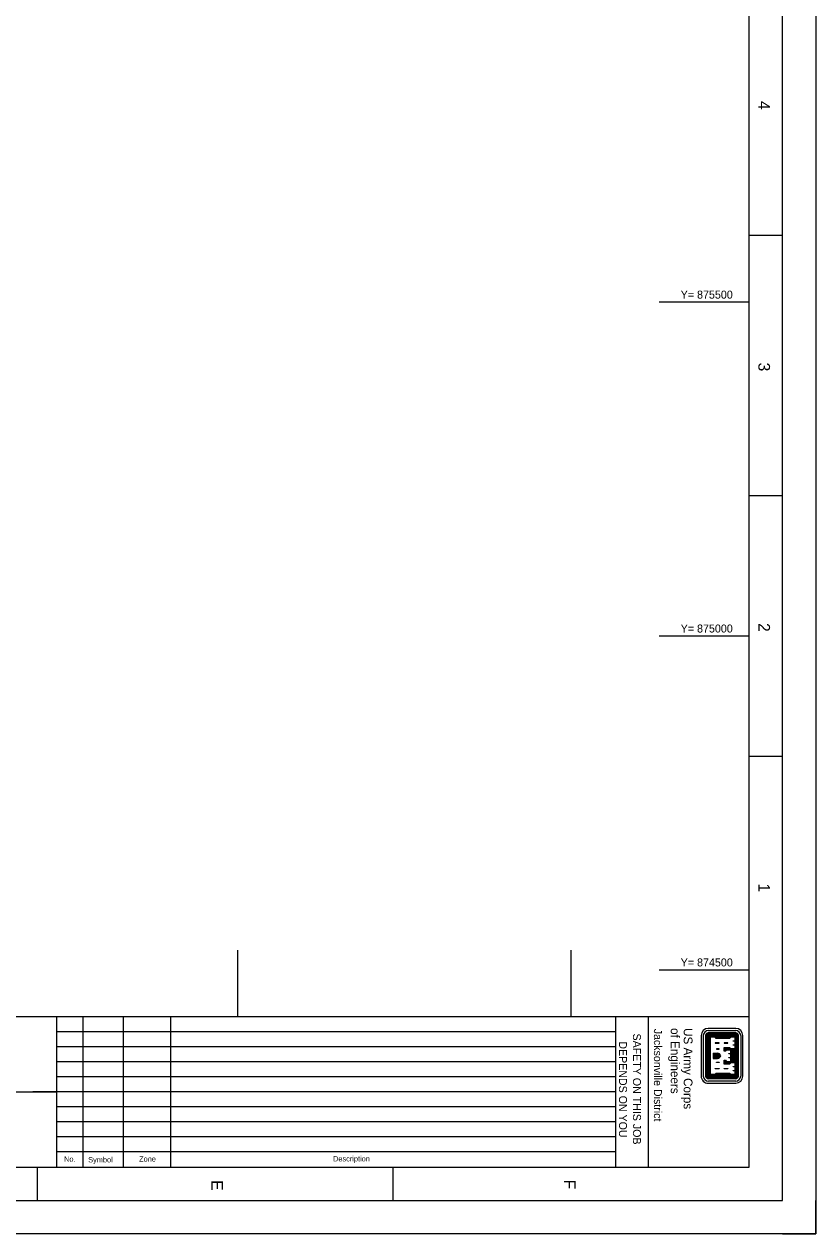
# Model space of a CAD drawing. Extents: x 573466 to 576866, y 874104 to 878505.
# Drawn here: x 575680 to 576866, y 874105 to 875916 of the extents above; entities that cross this region are included whole.
import ezdxf

# ---------------------------------------------------------------- set-up
doc = ezdxf.new("R2010")
doc.units = 0
for name, color, linetype in [('G-ANNO-NPLT', 7, 'Continuous'), ('G-ANNO-TEXT-LOGO', 7, 'Continuous'), ('G-ANNO-TEXT-TTLB', 7, 'Continuous'), ('G-ANNO-TTLB', 7, 'Continuous'), ('V-TOPO-COOR-STAT', 7, 'Continuous')]:
    doc.layers.add(name, color=color, linetype=linetype)

msp = doc.modelspace()

# ---------------------------------------------------------------- linework, layer by layer
at = {"layer": 'G-ANNO-NPLT'}
msp.add_lwpolyline([(576866.5, 878504.6), (576866.5, 874104.6), (573466.5, 874104.6), (573466.5, 878504.6)], close=True, dxfattribs=at)
msp.add_lwpolyline([(576816.5, 874104.6), (576866.5, 874104.6), (576866.5, 874154.6)], dxfattribs=at)
at = {"layer": 'G-ANNO-TEXT-LOGO'}
for p, q in [((576746.4, 874412.3), (576705.4, 874412.3)), ((576705.4, 874409.1), (576746.4, 874409.1)), ((576694.6, 874401.6), (576694.6, 874340.8)), ((576697.9, 874340.8), (576697.9, 874401.6)), ((576701.4, 874340.8), (576701.4, 874401.6)), ((576702.2, 874340.8), (576702.2, 874401.6)), ((576703.1, 874340.8), (576703.1, 874401.6)), ((576704, 874340.8), (576704, 874401.6)), ((576704.8, 874340.8), (576704.8, 874401.6)), ((576746.4, 874405.6), (576705.4, 874405.6)), ((576746.4, 874404.7), (576705.4, 874404.7)), ((576746.4, 874403.9), (576705.4, 874403.9)), ((576746.4, 874403), (576705.4, 874403)), ((576746.4, 874402.1), (576705.4, 874402.1)), ((576705.7, 874341.2), (576705.7, 874401.2)), ((576746.4, 874401.2), (576705.7, 874401.2)), ((576706.6, 874342), (576706.6, 874400.4)), ((576746.4, 874400.4), (576706.6, 874400.4)), ((576737.7, 874399.7), (576716.7, 874399.7)), ((576736.8, 874398.8), (576717.7, 874398.8)), ((576747, 874340.8), (576747, 874401.6)), ((576747.9, 874340.8), (576747.9, 874401.6)), ((576748.7, 874340.8), (576748.7, 874401.6)), ((576749.6, 874340.8), (576749.6, 874401.6)), ((576750.5, 874340.8), (576750.5, 874401.6)), ((576753.9, 874401.6), (576753.9, 874340.8)), ((576757.1, 874340.8), (576757.1, 874401.6)), ((576712.5, 874375.2), (576719.2, 874375.2)), ((576712.5, 874375.2), (576712.5, 874367.2)), ((576712.5, 874374.4), (576719.2, 874374.4)), ((576712.5, 874373.5), (576719.2, 874373.5)), ((576741, 874380.5), (576741, 874361.9)), ((576741.9, 874380.5), (576741.9, 874361.9)), ((576742.7, 874380.5), (576742.7, 874361.9)), ((576743.6, 874380.5), (576743.6, 874361.9)), ((576744.5, 874380.5), (576744.5, 874361.9)), ((576745.3, 874380.5), (576745.3, 874361.9)), ((576746.2, 874380.5), (576746.2, 874361.9)), ((576712.5, 874372.6), (576719.2, 874372.6)), ((576712.5, 874371.8), (576719.2, 874371.8)), ((576712.5, 874370.6), (576719.2, 874370.6)), ((576712.5, 874369.8), (576719.2, 874369.8)), ((576712.5, 874368.9), (576719.2, 874368.9)), ((576712.5, 874368), (576719.2, 874368)), ((576712.5, 874367.2), (576719.2, 874367.2)), ((576746.4, 874340.3), (576705.4, 874340.3)), ((576746.4, 874339.4), (576705.4, 874339.4)), ((576746.4, 874338.6), (576705.4, 874338.6)), ((576746.4, 874337.7), (576705.4, 874337.7)), ((576746.4, 874336.8), (576705.4, 874336.8)), ((576746.4, 874341.2), (576705.7, 874341.2)), ((576746.4, 874342), (576706.6, 874342)), ((576737.6, 874342.7), (576716.8, 874342.7)), ((576736.8, 874343.6), (576717.7, 874343.6)), ((576746.4, 874333.4), (576705.4, 874333.4)), ((576705.4, 874330.1), (576746.4, 874330.1))]:
    msp.add_line(p, q, dxfattribs=at)
for points in [[(576746.4, 874399.7), (576738.5, 874399.7), (576736.8, 874398), (576717.7, 874398), (576715.9, 874399.7), (576707.2, 874399.7), (576707.2, 874342.7), (576715.9, 874342.7), (576717.7, 874344.5), (576736.8, 874344.5), (576738.5, 874342.7), (576746.4, 874342.7), (576746.4, 874350.2), (576746.4, 874356), (576746.4, 874361.4), (576738.5, 874361.4), (576736.8, 874359.5), (576729.8, 874359.5), (576729.8, 874363.7), (576730.5, 874363.7), (576732.3, 874361.9), (576740.1, 874361.9), (576740.1, 874369.4), (576740.1, 874375.2), (576740.1, 874380.5), (576732.3, 874380.5), (576730.5, 874378.7), (576729.8, 874378.7), (576729.8, 874382.9), (576736.8, 874382.9), (576738.5, 874381.1), (576746.4, 874381.1), (576746.4, 874388.6), (576746.4, 874394.4), (576746.4, 874399.7)], [(576745.5, 874398.9), (576738.9, 874398.9), (576737.1, 874397.1), (576717.3, 874397.1), (576715.5, 874398.9), (576708.1, 874398.9), (576708.1, 874343.5), (576715.5, 874343.5), (576717.3, 874345.4), (576737.1, 874345.4), (576738.9, 874343.5), (576745.5, 874343.5), (576745.5, 874348.9), (576742.4, 874348.9), (576742.4, 874349.4), (576745.5, 874349.4), (576745.5, 874354.7), (576742.4, 874354.7), (576742.4, 874355.1), (576745.5, 874355.1), (576745.5, 874360.5), (576738.9, 874360.5), (576737.1, 874358.7), (576729, 874358.7), (576729, 874364.5), (576730.9, 874364.5), (576732.7, 874362.7), (576739.3, 874362.7), (576739.3, 874368.1), (576736.2, 874368.1), (576736.2, 874368.5), (576739.3, 874368.5), (576739.3, 874373.9), (576736.2, 874373.9), (576736.2, 874374.4), (576739.3, 874374.4), (576739.3, 874379.7), (576732.7, 874379.7), (576730.9, 874377.9), (576729, 874377.9), (576729, 874383.7), (576737.1, 874383.7), (576738.9, 874381.9), (576745.5, 874381.9), (576745.5, 874387.2), (576742.4, 874387.2), (576742.4, 874387.7), (576745.5, 874387.7), (576745.5, 874393.1), (576742.4, 874393.1), (576742.4, 874393.5), (576745.5, 874393.5), (576745.5, 874398.9)], [(576721.5, 874390.7), (576715.6, 874390.7), (576715.6, 874390.1), (576721.5, 874390.1), (576721.5, 874390.7)], [(576721.5, 874381.5), (576717.4, 874381.5), (576717.4, 874381), (576721.5, 874381), (576721.5, 874381.5)], [(576734.8, 874390.7), (576729, 874390.7), (576729, 874390.1), (576734.8, 874390.1), (576734.8, 874390.7)], [(576736.9, 874381.5), (576736.4, 874382), (576730.7, 874382), (576730.7, 874380.1), (576732, 874381.4), (576737, 874381.4)], [(576721.5, 874360.9), (576717.4, 874360.9), (576717.4, 874361.4), (576721.5, 874361.4), (576721.5, 874360.9)], [(576736.9, 874360.9), (576736.4, 874360.4), (576730.7, 874360.4), (576730.7, 874362.2), (576732, 874361), (576737, 874361)], [(576721.5, 874351.8), (576715.6, 874351.8), (576715.6, 874352.3), (576721.5, 874352.3), (576721.5, 874351.8)], [(576734.8, 874351.8), (576729, 874351.8), (576729, 874352.3), (576734.8, 874352.3), (576734.8, 874351.8)]]:
    msp.add_lwpolyline(points, dxfattribs=at)
for centre, major_axis, start_param, end_param in [((576705.3, 874401.5), (0, 10.7), 6.28317, 7.853966), ((576705.3, 874401.5), (0, 7.49), 6.28317, 7.853966), ((576746.4, 874401.5), (0, -10.7), 1.57078, 3.141576), ((576746.4, 874401.5), (0, -7.49), 1.57078, 3.141576), ((576705.3, 874401.5), (0, 4.02), 6.28317, 7.853966), ((576705.3, 874401.5), (0, 3.15), 6.28317, 7.853966), ((576705.3, 874401.5), (0, 2.28), 6.28317, 7.853966), ((576705.3, 874401.5), (0, 1.41), 6.28317, 7.853966), ((576705.3, 874401.5), (0, 0.546), 6.28317, 7.853966), ((576746.4, 874401.5), (0, -4.02), 1.57078, 3.141576), ((576746.4, 874401.5), (0, -3.15), 1.57078, 3.141576), ((576746.4, 874401.5), (0, -2.28), 1.57078, 3.141576), ((576746.4, 874401.5), (0, -1.41), 1.57078, 3.141576), ((576746.4, 874401.5), (0, -0.546), 1.57078, 3.141576), ((576718.7, 874369.7), (0, 3.82), 4.947465, 6.21436), ((576718.7, 874369.7), (0, 5.55), 4.985832, 6.214359), ((576718.7, 874369.7), (0, 4.69), 4.947465, 6.21436), ((576718.7, 874369.7), (0, 2.95), 4.947465, 6.21436), ((576718.7, 874372.7), (0, -2.08), 0.068794, 1.335689), ((576718.7, 874372.7), (0, -2.95), 0.068794, 1.335689), ((576718.7, 874369.7), (0, 2.08), 4.947465, 6.214359), ((576718.7, 874372.7), (0, -3.82), 0.068795, 1.335689), ((576718.7, 874372.7), (0, -4.69), 0.068795, 1.335689), ((576718.7, 874372.7), (0, -5.55), 0.068795, 1.29842), ((576705.3, 874340.8), (0, -10.7), 4.712373, 6.28317), ((576705.3, 874340.8), (0, 7.49), 1.570781, 3.141577), ((576705.3, 874340.8), (0, -4.02), 4.712373, 6.28317), ((576705.3, 874340.8), (0, -3.15), 4.712373, 6.28317), ((576705.3, 874340.8), (0, -2.28), 4.712373, 6.28317), ((576705.3, 874340.8), (0, -1.41), 4.712373, 6.28317), ((576705.3, 874340.8), (0, -0.546), 4.712373, 6.28317), ((576746.4, 874340.8), (0, -4.02), 6.283169, 7.853965), ((576746.4, 874340.8), (0, -3.15), 6.283169, 7.853965), ((576746.4, 874340.8), (0, -2.28), 6.283169, 7.853965), ((576746.4, 874340.8), (0, -1.41), 6.283169, 7.853965), ((576746.4, 874340.8), (0, -0.546), 6.283169, 7.853965), ((576746.4, 874340.8), (0, -10.7), 6.283169, 7.853965), ((576746.4, 874340.8), (0, -7.49), 6.28317, 7.853966)]:
    msp.add_ellipse(centre, major_axis=major_axis, ratio=0.99964, start_param=start_param, end_param=end_param, dxfattribs=at)
at = {"layer": 'G-ANNO-TTLB'}
for p, q in [((576816.5, 875599.6), (576766.5, 875599.6)), ((576816.5, 875209.6), (576766.5, 875209.6)), ((576816.5, 874819.6), (576766.5, 874819.6)), ((576766.5, 874429.6), (573566.5, 874429.6)), ((575728.2, 874429.6), (575728.2, 874204.6)), ((575768.1, 874429.6), (575768, 874204.6)), ((575828.1, 874429.6), (575828.1, 874204.6)), ((575899.2, 874429.6), (575899.2, 874204.6)), ((576566.1, 874430.2), (576566.1, 874205.2)), ((576615.2, 874429.6), (576615.2, 874204.6)), ((576566.1, 874407.3), (575728.2, 874407.3)), ((576566.1, 874384.8), (575728.2, 874384.8)), ((576566.1, 874362.3), (575728.2, 874362.3)), ((576566.1, 874339.8), (575728.2, 874339.8)), ((574868.6, 874317.8), (575728.2, 874317.1)), ((575728.2, 874317.1), (575692.8, 874317.1)), ((576566.1, 874317.3), (575728.2, 874317.3)), ((576566.1, 874294.8), (575728.2, 874294.8)), ((576566.1, 874272.3), (575728.2, 874272.3)), ((576566.1, 874249.8), (575728.2, 874249.8)), ((576566.1, 874227.3), (575728.2, 874227.3)), ((575699.7, 874154.6), (575699.7, 874204.6)), ((576233, 874154.6), (576233, 874204.6))]:
    msp.add_line(p, q, dxfattribs=at)
for points in [[(573516.5, 878454.6), (573516.5, 874154.6), (576816.5, 874154.6), (576816.5, 878454.6)], [(576766.5, 874204.6), (576766.5, 878329.6), (573566.5, 878329.6), (573566.5, 874204.6)]]:
    msp.add_lwpolyline(points, close=True, dxfattribs=at)
at = {"layer": 'V-TOPO-COOR-STAT'}
for p, q in [((576631.5, 875500), (576767, 875500)), ((576631.5, 875000), (576767, 875000)), ((576000, 874429.6), (576000, 874529.6)), ((576500, 874429.6), (576500, 874529.6)), ((576631.5, 874500), (576767, 874500))]:
    msp.add_line(p, q, dxfattribs=at)

# ---------------------------------------------------------------- texts
at = {"layer": 'G-ANNO-TEXT-TTLB'}
for s, height, rotation, p in [('Jacksonville District', 11.9, 270, (576623.8, 874411.7)), ('of Engineers', 13.086, 270, (576649.1, 874412.7)), ('US Army Corps', 13.086, 270, (576668.5, 874412.7)), ('DEPENDS ON YOU', 11.9, 270, (576571.5, 874392.8)), ('SAFETY ON THIS JOB', 11.9, 270, (576592.4, 874404.5)), ('No.', 8, 360, (575739.8, 874212.5)), ('Symbol', 8, 360, (575775.9, 874211.5)), ('Zone', 8, 360, (575852.2, 874212.7)), ('Description', 8, 360, (576142.9, 874213))]:
    msp.add_text(s, height=height, rotation=rotation, dxfattribs=at).set_placement(p)
at = {"layer": 'G-ANNO-TTLB'}
for s, p in [('4', (576780.3, 875800.9)), ('3', (576780.3, 875409.2)), ('2', (576780.3, 875019.2)), ('1', (576780.3, 874629.2)), ('E', (575960.3, 874185)), ('F', (576489.1, 874185.8))]:
    msp.add_text(s, height=17.5, rotation=270, dxfattribs=at).set_placement(p)
at = {"layer": 'V-TOPO-COOR-STAT'}
for s, p in [('Y= 875500', (576663.9, 875505)), ('Y= 875000', (576663.9, 875005)), ('Y= 874500', (576663.9, 874505))]:
    msp.add_text(s, height=12, dxfattribs=at).set_placement(p)

doc.saveas('drawing.dxf')
